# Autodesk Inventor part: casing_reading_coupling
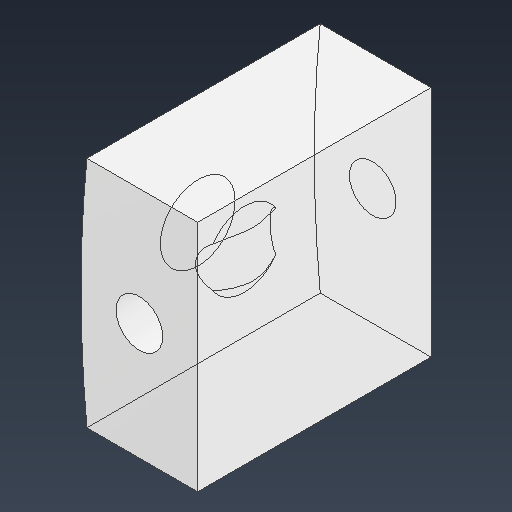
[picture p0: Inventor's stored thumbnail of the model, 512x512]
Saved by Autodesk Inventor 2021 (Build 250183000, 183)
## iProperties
Created: 2020-09
Part Number: casing_reading_coupling
Material: SOLIDWORKS Materials|Perspex (TM) GS Acrylic Cast Sheet
Document SubType Name: Modeling
Designer: ftrauzettel
Density: 1.19 g/cm^3
Appearance: 255,255,255
Author: ftrauzettel
Sending System: SolidWorks 2016
Last Author: Pam
Last Saved: 2020-09-13
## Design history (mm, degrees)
feature "Tap Drill for M2 Tap2"
body "Solid1"
